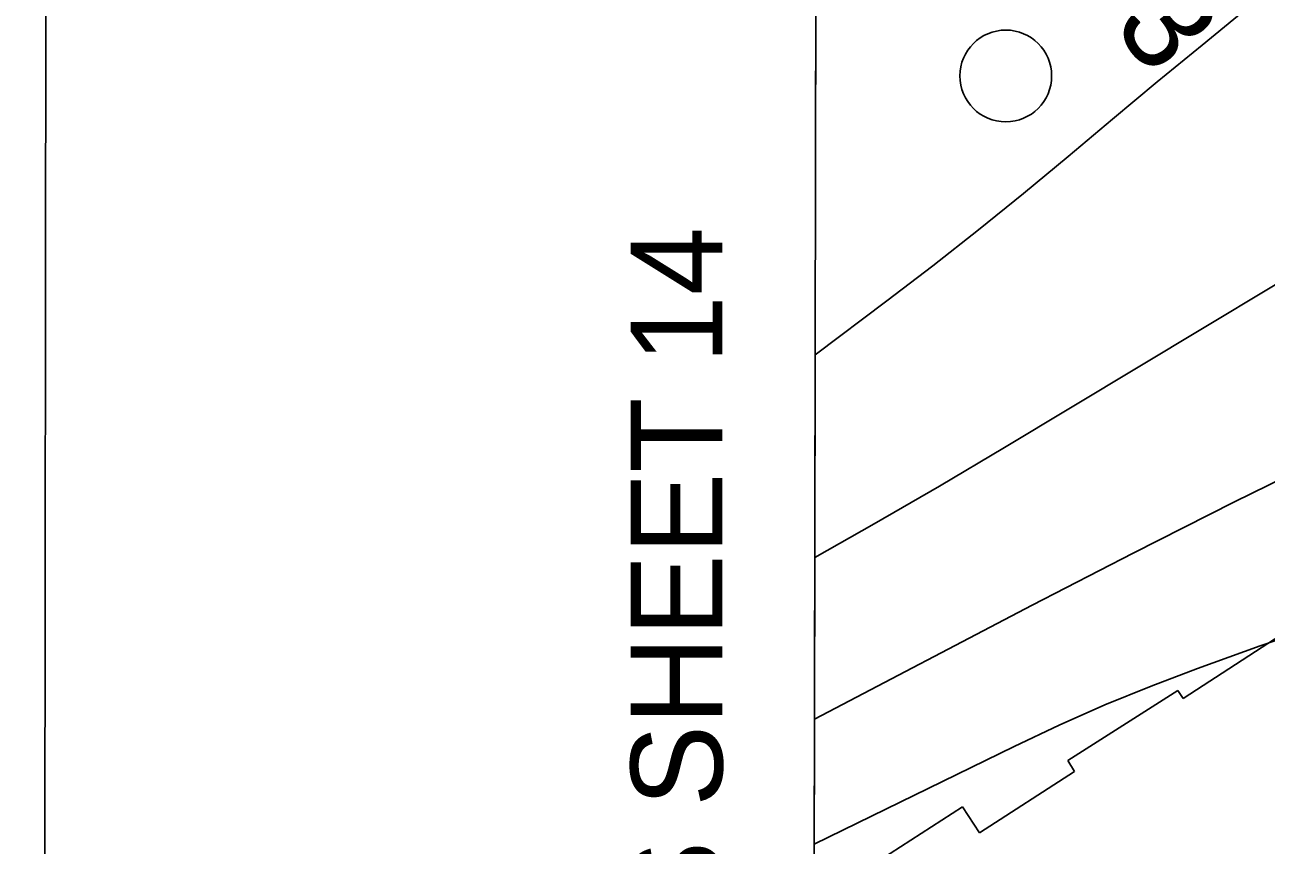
# Model space of a CAD drawing. Extents: x 3208593 to 3246461, y 812903 to 838290.
# Drawn here: x 3211927 to 3213280, y 829085 to 829979 of the extents above; entities that cross this region are included whole.
import ezdxf

# ---------------------------------------------------------------- set-up
doc = ezdxf.new("R2010")
doc.units = 0
for name, color, linetype in [('V-ANNO-SYMB', 7, 'Continuous'), ('V-ANNO-TEXT', 7, 'Continuous'), ('V-GRID-FRAM', 7, 'Continuous'), ('V-RIVR-IDEN', 7, 'Continuous'), ('V-RIVR-MILE', 7, 'Continuous'), ('V-RRAP-RVMT', 7, 'Continuous'), ('V-RRAP-RVMT-IDEN', 7, 'Continuous'), ('V-TOPO-DPTH', 7, 'Continuous'), ('V-TOPO-MAJR', 7, 'Continuous'), ('V-TOPO-MINR', 7, 'Continuous')]:
    doc.layers.add(name, color=color, linetype=linetype)

msp = doc.modelspace()

# ---------------------------------------------------------------- linework, layer by layer
at = {"layer": 'V-ANNO-SYMB'}
msp.add_lwpolyline([(3211927.1, 814160.7), (3245010.3, 814112.6), (3245043.6, 837029.1), (3211960.5, 837077.3), (3211927.1, 814160.7)], dxfattribs=at)
at = {"layer": 'V-GRID-FRAM'}
msp.add_lwpolyline([(3212801.6, 836513), (3244200.9, 836467.3), (3244182.3, 818280.5), (3212767.2, 818326.1), (3212801.6, 836513)], dxfattribs=at)
at = {"layer": 'V-RIVR-MILE'}
msp.add_circle((3212996.4, 829923.3), 50, dxfattribs=at)
at = {"layer": 'V-RRAP-RVMT'}
for p, q in [((3213189.8, 829244.9), (3213386.5, 829373)), ((3213064, 829177.3), (3213183.8, 829253.6)), ((3213183.8, 829253.6), (3213189.8, 829244.9)), ((3213071.2, 829165.6), (3213064, 829177.3)), ((3212967.7, 829098.7), (3213071.2, 829165.6)), ((3212836.5, 829054.4), (3212949.4, 829127.1)), ((3212949.4, 829127.1), (3212967.7, 829098.7))]:
    msp.add_line(p, q, dxfattribs=at)
at = {"layer": 'V-TOPO-DPTH'}
for points in [[(3213259.3, 829996.9), (3213210.3, 829956.9), (3213161.5, 829916.8), (3213112.8, 829876.4), (3213064.4, 829835.7), (3213015.7, 829795.4), (3212966.6, 829755.6), (3212916.8, 829716.6), (3212866.6, 829678.2), (3212788.6, 829619.4), (3212789.7, 830238.9)], [(3213259.3, 829996.9), (3213210.3, 829956.9), (3213161.5, 829916.8), (3213112.8, 829876.4), (3213064.4, 829835.7), (3213015.7, 829795.4), (3212966.6, 829755.6), (3212916.8, 829716.6), (3212866.6, 829678.2), (3212788.6, 829619.4)], [(3212788.6, 829619.4), (3212788.2, 829398.7), (3212853, 829435.2), (3212924.1, 829476.5), (3212995, 829518.4), (3213504, 829824.3), (3213526.1, 829837.7), (3213548.2, 829851.2), (3213570.1, 829864.9), (3213592, 829878.6), (3213660.8, 829922.3), (3213717.3, 829957.4), (3213774.3, 829991.8)], [(3212788.2, 829398.7), (3212853, 829435.2), (3212924.1, 829476.5), (3212995, 829518.4), (3213504, 829824.3), (3213526.1, 829837.7), (3213548.2, 829851.2), (3213570.1, 829864.9), (3213592, 829878.6), (3213660.8, 829922.3), (3213717.3, 829957.4), (3213774.3, 829991.8)], [(3213307, 828996.7), (3213230.6, 828955.6), (3213154.3, 828914.3), (3213078.3, 828872.6), (3213002.3, 828830.7), (3212880.3, 828763.1), (3212865.5, 828754.8), (3212850.8, 828746.4), (3212836, 828738), (3212821.4, 828729.4), (3212786.9, 828709.2), (3212788.2, 829398.7)]]:
    msp.add_lwpolyline(points, dxfattribs=at)
at = {"layer": 'V-TOPO-MAJR'}
msp.add_lwpolyline([(3212787.8, 829222.5), (3213025, 829346.6), (3213135.1, 829403.4), (3213245.7, 829459.3), (3213356.9, 829513.9)], dxfattribs=at)
at = {"layer": 'V-TOPO-MINR'}
for points in [[(3213259.3, 829996.9), (3213210.3, 829956.9), (3213161.5, 829916.8), (3213112.8, 829876.4), (3213064.4, 829835.7), (3213015.7, 829795.4), (3212966.6, 829755.6), (3212916.8, 829716.6), (3212866.6, 829678.2), (3212788.6, 829619.4)], [(3212788.2, 829398.7), (3212853, 829435.2), (3212924.1, 829476.5), (3212995, 829518.4), (3213504, 829824.3), (3213526.1, 829837.7), (3213548.2, 829851.2), (3213570.1, 829864.9), (3213592, 829878.6), (3213660.8, 829922.3), (3213717.3, 829957.4), (3213774.3, 829991.8)], [(3212787.6, 829086.3), (3213005.5, 829192.8), (3213054.7, 829215.9), (3213104.3, 829238), (3213154.7, 829258.4), (3213205.5, 829277.7), (3213239.5, 829290.1), (3213273.7, 829302.2), (3213308, 829314)]]:
    msp.add_lwpolyline(points, dxfattribs=at)

# ---------------------------------------------------------------- texts
at = {"layer": 'V-ANNO-TEXT'}
msp.add_text('JOINS SHEET 14', height=100, rotation=90, dxfattribs=at).set_placement((3212687.6, 828696))
at = {"layer": 'V-RIVR-IDEN'}
msp.add_text('283', height=100, rotation=307.5866, dxfattribs=at).set_placement((3213020.8, 830096.9))
at = {"layer": 'V-RRAP-RVMT-IDEN'}
msp.add_text('IOWA ', height=100, rotation=30.4153, dxfattribs=at).set_placement((3213246.3, 828866.2))

doc.saveas('drawing.dxf')
